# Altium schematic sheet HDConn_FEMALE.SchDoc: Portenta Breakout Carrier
size A3; Author: S. Navaretti; DocumentNumber: ASX00031; Revision: V1.3; SheetNumber: 2; SheetTotal: 6; RevAuthor: Silvio Navaretti
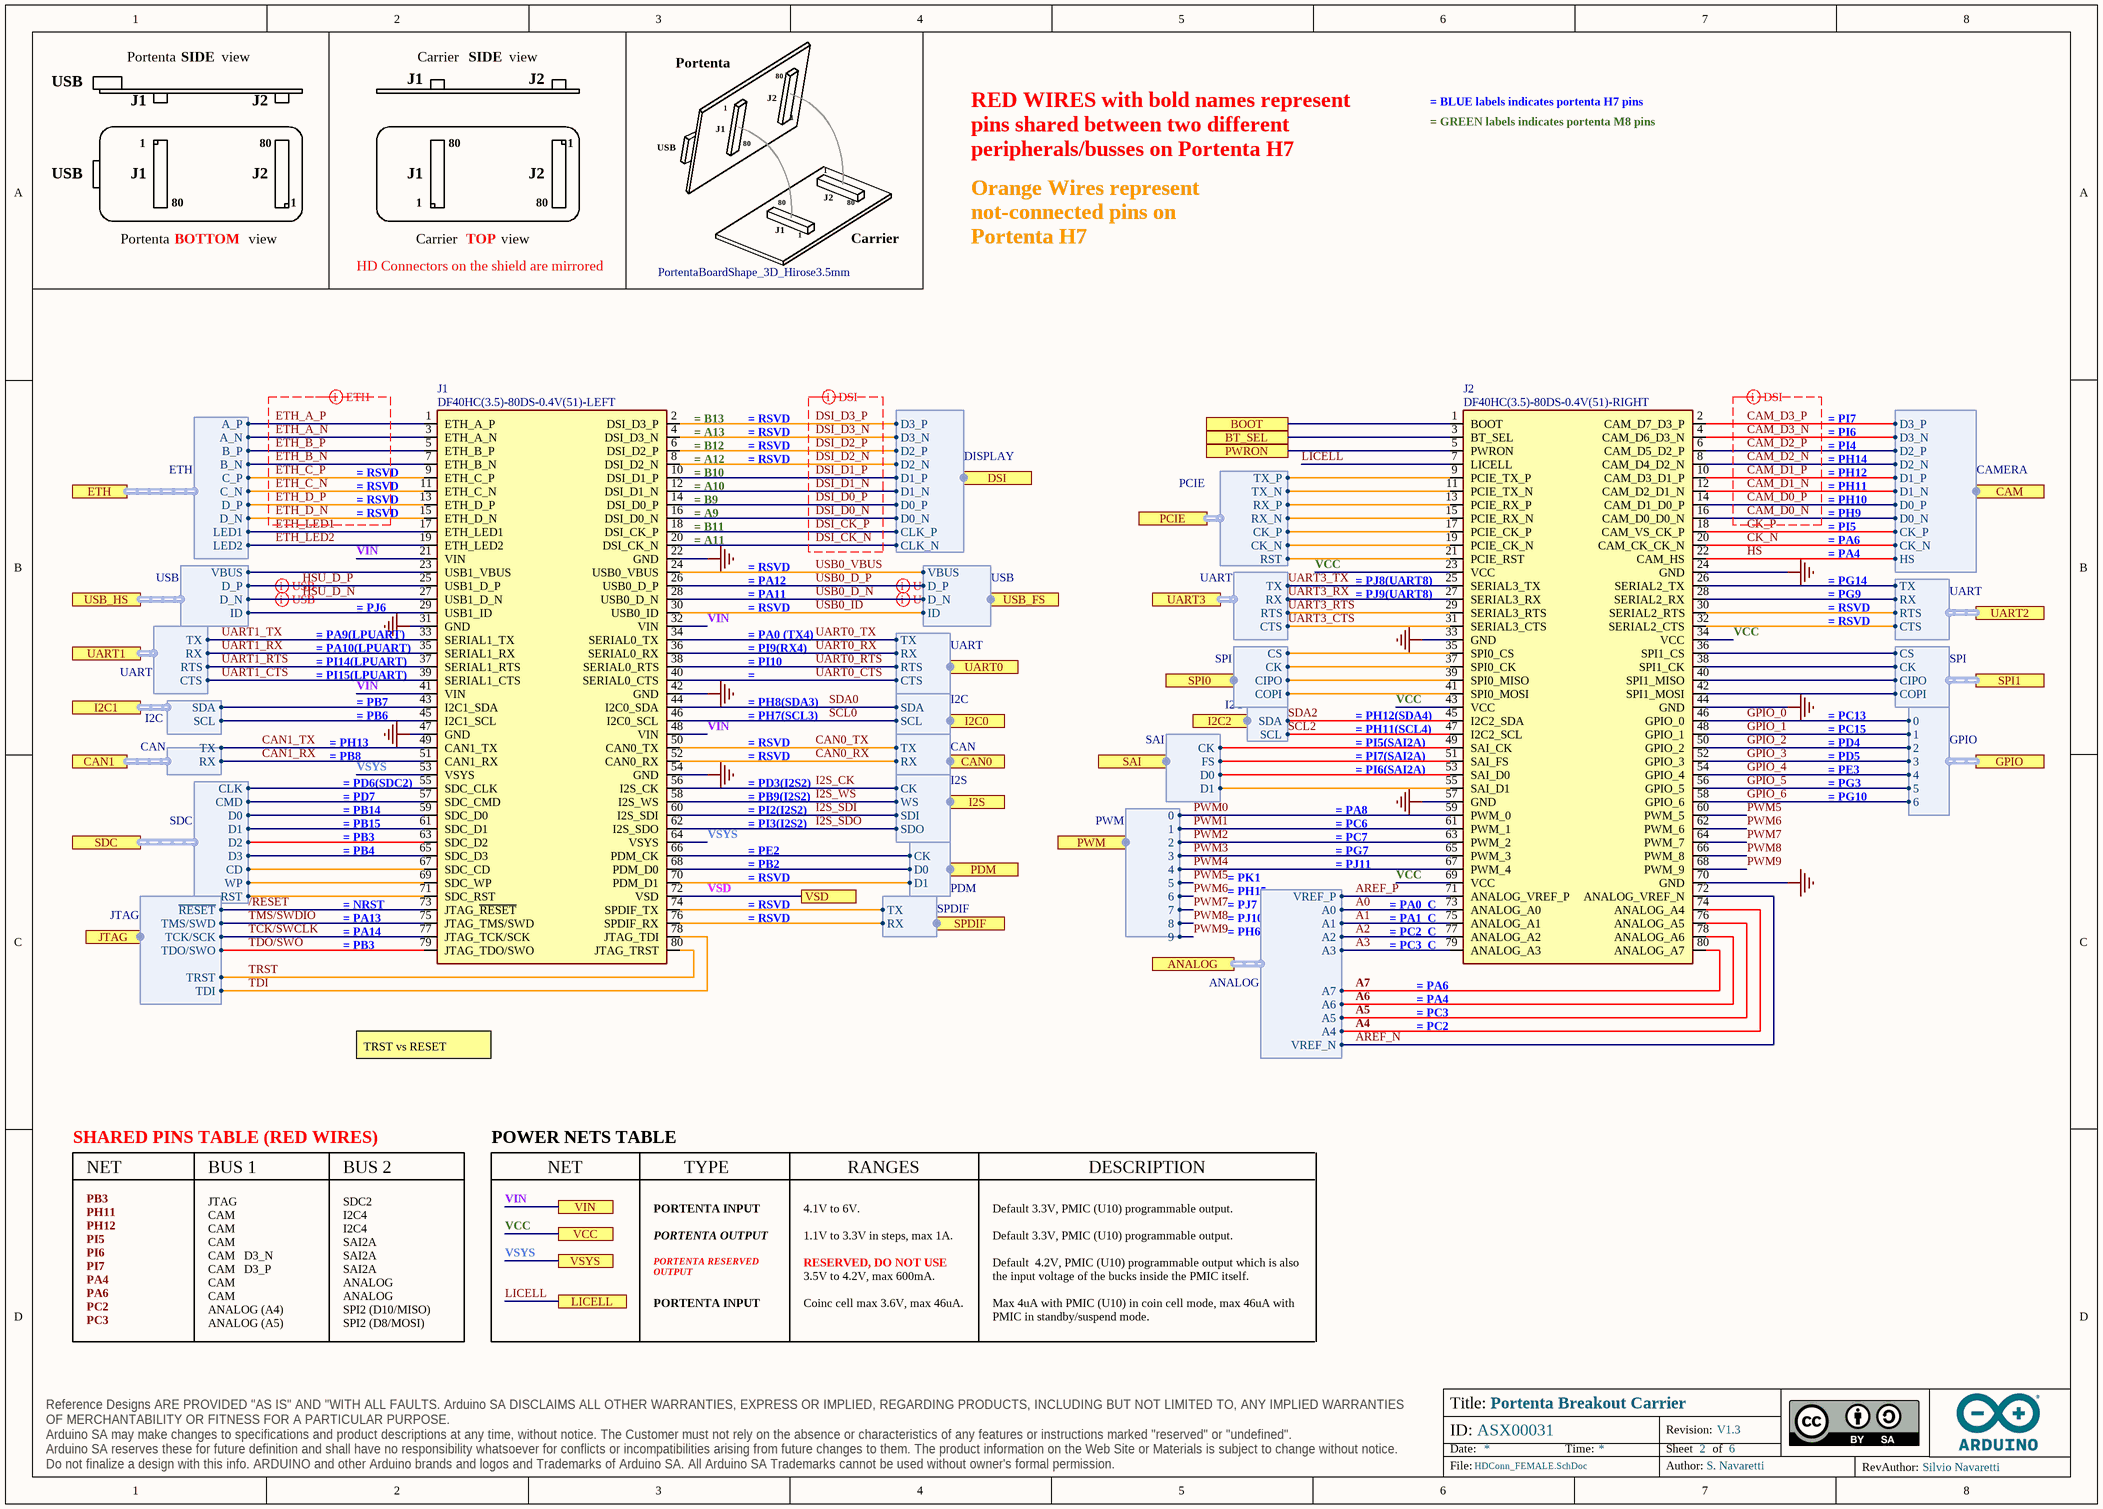
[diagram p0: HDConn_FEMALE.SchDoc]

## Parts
J1  DF40HC(3.5)-80DS-0.4V(51)-LEFT  [DF40HC(3.5)-80DS-0.4V(51)-Footprint-1]
J2  DF40HC(3.5)-80DS-0.4V(51)-RIGHT  [DF40HC(3.5)-80DS-0.4V(51)-Footprint-1]
PortentaBoardShape_3D_Hirose3.5mm  PortentaBoardShape_3D_Hirose3.5mm  [PortentaBoardShape3D-Footprint-1]  (no BOM)

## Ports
ANALOG (harness ANALOG), BOOT, BT_SEL, CAM (harness CAMERA), CAN0 (harness CAN), CAN1 (harness CAN), DSI (harness DISPLAY), ETH (harness ETH), GPIO (harness GPIO), I2C0 (harness I2C), I2C1 (harness I2C), I2C2 (harness I2C), I2S (harness I2S), JTAG (harness JTAG), LICELL, PCIE (harness PCIE), PDM (harness PDM), PWM (harness PWM), PWRON, SAI (harness SAI), SDC (harness SDC), SPDIF (harness SPDIF), SPI0 (harness SPI), SPI1 (harness SPI), UART0 (harness UART), UART1 (harness UART), UART2 (harness UART), UART3 (harness UART), USB_FS (harness USB), USB_HS (harness USB), VCC, VIN, VSD, VSYS

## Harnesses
ANALOG: VREF_P, A0, A1, A2, A3, A7, A6, A5, A4, VREF_N
PWM: 0, 1, 2, 3, 4, 5, 6, 7, 8, 9
GPIO: 0, 1, 2, 3, 4, 5, 6
ETH: A_P, A_N, B_P, B_N, C_P, C_N, D_P, D_N, LED1, LED2
USB: VBUS, D_P, D_N, ID
UART: RX, TX, RTS, CTS
I2C: SCL, SDA
CAN: RX, TX
SDC: CLK, CMD, D0, D1, D2, D3, CD, WP, RST
JTAG: ~{RESET}, TCK/SCK, TDI, TDO/SWO, TMS/SWD, TRST
DISPLAY: CLK_N, CLK_P, D0_N, D0_P, D1_N, D1_P, D2_N, D2_P, D3_N, D3_P
I2C: SDA, SCL
I2S: CK, SDI, SDO, WS
PDM: CK, D0, D1
SAI: CK, FS, D0, D1
CAMERA: D3_P, D3_N, D2_P, D2_N, D1_P, D1_N, D0_P, D0_N, CK_P, CK_N, HS
SPI: CS, CK, CIPO, COPI
PCIE: TX_P, TX_N, RX_P, RX_N, CK_P, CK_N, RST
SPDIF: RX, TX

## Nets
GND: J1.22(GND) J1.31(GND) J1.42(GND) J1.47(GND) J1.54(GND) J2.24(GND) J2.33(GND) J2.44(GND) J2.57(GND) J2.70(GND)
/RESET: J1.73(JTAG_~{RESET}) ; port JTAG.~{RESET}
A0: J2.73(ANALOG_A0) ; port ANALOG.A0
A1: J2.75(ANALOG_A1) ; port ANALOG.A1
A2: J2.77(ANALOG_A2) ; port ANALOG.A2
A3: J2.79(ANALOG_A3) ; port ANALOG.A3
A4: J2.74(ANALOG_A4) ; port ANALOG.A4
A5: J2.76(ANALOG_A5) ; port ANALOG.A5
A6: J2.78(ANALOG_A6) ; port ANALOG.A6
A7: J2.80(ANALOG_A7) ; port ANALOG.A7
AREF_N: J2.72(ANALOG_VREF_N) ; port ANALOG.VREF_N
AREF_P: J2.71(ANALOG_VREF_P) ; port ANALOG.VREF_P
BOOT: J2.1(BOOT) ; port BOOT
BT_SEL: J2.3(BT_SEL) ; port BT_SEL
CAM_D0_N: J2.16(CAM_D0_D0_N) ; port CAM.D0_N
CAM_D0_P: J2.14(CAM_D1_D0_P) ; port CAM.D0_P
CAM_D1_N: J2.12(CAM_D2_D1_N) ; port CAM.D1_N
CAM_D1_P: J2.10(CAM_D3_D1_P) ; port CAM.D1_P
CAM_D2_N: J2.8(CAM_D4_D2_N) ; port CAM.D2_N
CAM_D2_P: J2.6(CAM_D5_D2_P) ; port CAM.D2_P
CAM_D3_N: J2.4(CAM_D6_D3_N) ; port CAM.D3_N
CAM_D3_P: J2.2(CAM_D7_D3_P) ; port CAM.D3_P
CAN0_RX: J1.52(CAN0_RX) ; port CAN0.RX
CAN0_TX: J1.50(CAN0_TX) ; port CAN0.TX
CAN1_RX: J1.51(CAN1_RX) ; port CAN1.RX
CAN1_TX: J1.49(CAN1_TX) ; port CAN1.TX
CK_N: J2.20(CAM_CK_CK_N) ; port CAM.CK_N
CK_P: J2.18(CAM_VS_CK_P) ; port CAM.CK_P
DSI_CK_N: J1.20(DSI_CK_N) ; port DSI.CLK_N
DSI_CK_P: J1.18(DSI_CK_P) ; port DSI.CLK_P
DSI_D0_N: J1.16(DSI_D0_N) ; port DSI.D0_N
DSI_D0_P: J1.14(DSI_D0_P) ; port DSI.D0_P
DSI_D1_N: J1.12(DSI_D1_N) ; port DSI.D1_N
DSI_D1_P: J1.10(DSI_D1_P) ; port DSI.D1_P
DSI_D2_N: J1.8(DSI_D2_N) ; port DSI.D2_N
DSI_D2_P: J1.6(DSI_D2_P) ; port DSI.D2_P
DSI_D3_N: J1.4(DSI_D3_N) ; port DSI.D3_N
DSI_D3_P: J1.2(DSI_D3_P) ; port DSI.D3_P
ETH_A_N: J1.3(ETH_A_N) ; port ETH.A_N
ETH_A_P: J1.1(ETH_A_P) ; port ETH.A_P
ETH_B_N: J1.7(ETH_B_N) ; port ETH.B_N
ETH_B_P: J1.5(ETH_B_P) ; port ETH.B_P
ETH_C_N: J1.11(ETH_C_N) ; port ETH.C_N
ETH_C_P: J1.9(ETH_C_P) ; port ETH.C_P
ETH_D_N: J1.15(ETH_D_N) ; port ETH.D_N
ETH_D_P: J1.13(ETH_D_P) ; port ETH.D_P
ETH_LED1: J1.17(ETH_LED1) ; port ETH.LED1
ETH_LED2: J1.19(ETH_LED2) ; port ETH.LED2
GPIO_0: J2.46(GPIO_0) ; port GPIO.0
GPIO_1: J2.48(GPIO_1) ; port GPIO.1
GPIO_2: J2.50(GPIO_2) ; port GPIO.2
GPIO_3: J2.52(GPIO_3) ; port GPIO.3
GPIO_4: J2.54(GPIO_4) ; port GPIO.4
GPIO_5: J2.56(GPIO_5) ; port GPIO.5
GPIO_6: J2.58(GPIO_6) ; port GPIO.6
HS: J2.22(CAM_HS) ; port CAM.HS
HSU_D_N: J1.27(USB1_D_N) ; port USB_HS.D_N
HSU_D_P: J1.25(USB1_D_P) ; port USB_HS.D_P
I2S_CK: J1.56(I2S_CK) ; port I2S.CK
I2S_SDI: J1.60(I2S_SDI) ; port I2S.SDI
I2S_SDO: J1.62(I2S_SDO) ; port I2S.SDO
I2S_WS: J1.58(I2S_WS) ; port I2S.WS
LICELL: J2.7(LICELL) ; port LICELL
PWM0: J2.59(PWM_0) ; port PWM.0
PWM1: J2.61(PWM_1) ; port PWM.1
PWM2: J2.63(PWM_2) ; port PWM.2
PWM3: J2.65(PWM_3) ; port PWM.3
PWM4: J2.67(PWM_4) ; port PWM.4
PWM5: J2.60(PWM_5) ; port PWM.5
PWM6: J2.62(PWM_6) ; port PWM.6
PWM7: J2.64(PWM_7) ; port PWM.7
PWM8: J2.66(PWM_8) ; port PWM.8
PWM9: J2.68(PWM_9) ; port PWM.9
PWRON: J2.5(PWRON) ; port PWRON
SCL0: J1.46(I2C0_SCL) ; port I2C0.SCL
SCL2: J2.47(I2C2_SCL) ; port I2C2.SCL
SDA0: J1.44(I2C0_SDA) ; port I2C0.SDA
SDA2: J2.45(I2C2_SDA) ; port I2C2.SDA
TCK/SWCLK: J1.77(JTAG_TCK/SCK) ; port JTAG.TCK/SCK
TDI: J1.78(JTAG_TDI) ; port JTAG.TDI
TDO/SWO: J1.79(JTAG_TDO/SWO) ; port JTAG.TDO/SWO
TMS/SWDIO: J1.75(JTAG_TMS/SWD) ; port JTAG.TMS/SWD
TRST: J1.80(JTAG_TRST) ; port JTAG.TRST
UART0_CTS: J1.40(SERIAL0_CTS) ; port UART0.CTS
UART0_RTS: J1.38(SERIAL0_RTS) ; port UART0.RTS
UART0_RX: J1.36(SERIAL0_RX) ; port UART0.RX
UART0_TX: J1.34(SERIAL0_TX) ; port UART0.TX
UART1_CTS: J1.39(SERIAL1_CTS) ; port UART1.CTS
UART1_RTS: J1.37(SERIAL1_RTS) ; port UART1.RTS
UART1_RX: J1.35(SERIAL1_RX) ; port UART1.RX
UART1_TX: J1.33(SERIAL1_TX) ; port UART1.TX
UART3_CTS: J2.31(SERIAL3_CTS) ; port UART3.CTS
UART3_RTS: J2.29(SERIAL3_RTS) ; port UART3.RTS
UART3_RX: J2.27(SERIAL3_RX) ; port UART3.RX
UART3_TX: J2.25(SERIAL3_TX) ; port UART3.TX
USB0_D_N: J1.28(USB0_D_N) ; port USB_FS.D_N
USB0_D_P: J1.26(USB0_D_P) ; port USB_FS.D_P
USB0_ID: J1.30(USB0_ID) ; port USB_FS.ID
USB0_VBUS: J1.24(USB0_VBUS) ; port USB_FS.VBUS
VCC: J2.23(VCC) J2.34(VCC) J2.43(VCC) J2.69(VCC) ; port VCC
VIN: J1.21(VIN) J1.32(VIN) J1.41(VIN) J1.48(VIN) ; port VIN
VSD: J1.72(VSD) ; port VSD
VSYS: J1.53(VSYS) J1.64(VSYS) ; port VSYS
NetJ1_23: J1.23(USB1_VBUS) ; port USB_HS.VBUS
NetJ1_29: J1.29(USB1_ID) ; port USB_HS.ID
NetJ1_43: J1.43(I2C1_SDA) ; port I2C1.SDA
NetJ1_45: J1.45(I2C1_SCL) ; port I2C1.SCL
NetJ1_55: J1.55(SDC_CLK) ; port SDC.CLK
NetJ1_57: J1.57(SDC_CMD) ; port SDC.CMD
NetJ1_59: J1.59(SDC_D0) ; port SDC.D0
NetJ1_61: J1.61(SDC_D1) ; port SDC.D1
NetJ1_63: J1.63(SDC_D2) ; port SDC.D2
NetJ1_65: J1.65(SDC_D3) ; port SDC.D3
NetJ1_66: J1.66(PDM_CK) ; port PDM.CK
NetJ1_67: J1.67(SDC_CD) ; port SDC.CD
NetJ1_68: J1.68(PDM_D0) ; port PDM.D0
NetJ1_69: J1.69(SDC_WP) ; port SDC.WP
NetJ1_70: J1.70(PDM_D1) ; port PDM.D1
NetJ1_71: J1.71(SDC_RST) ; port SDC.RST
NetJ1_74: J1.74(SPDIF_TX) ; port SPDIF.TX
NetJ1_76: J1.76(SPDIF_RX) ; port SPDIF.RX
NetJ2_9: J2.9(PCIE_TX_P) ; port PCIE.TX_P
NetJ2_11: J2.11(PCIE_TX_N) ; port PCIE.TX_N
NetJ2_13: J2.13(PCIE_RX_P) ; port PCIE.RX_P
NetJ2_15: J2.15(PCIE_RX_N) ; port PCIE.RX_N
NetJ2_17: J2.17(PCIE_CK_P) ; port PCIE.CK_P
NetJ2_19: J2.19(PCIE_CK_N) ; port PCIE.CK_N
NetJ2_21: J2.21(PCIE_RST) ; port PCIE.RST
NetJ2_26: J2.26(SERIAL2_TX) ; port UART2.TX
NetJ2_28: J2.28(SERIAL2_RX) ; port UART2.RX
NetJ2_30: J2.30(SERIAL2_RTS) ; port UART2.RTS
NetJ2_32: J2.32(SERIAL2_CTS) ; port UART2.CTS
NetJ2_35: J2.35(SPI0_CS) ; port SPI0.CS
NetJ2_36: J2.36(SPI1_CS) ; port SPI1.CS
NetJ2_37: J2.37(SPI0_CK) ; port SPI0.CK
NetJ2_38: J2.38(SPI1_CK) ; port SPI1.CK
NetJ2_39: J2.39(SPI0_MISO) ; port SPI0.CIPO
NetJ2_40: J2.40(SPI1_MISO) ; port SPI1.CIPO
NetJ2_41: J2.41(SPI0_MOSI) ; port SPI0.COPI
NetJ2_42: J2.42(SPI1_MOSI) ; port SPI1.COPI
NetJ2_49: J2.49(SAI_CK) ; port SAI.CK
NetJ2_51: J2.51(SAI_FS) ; port SAI.FS
NetJ2_53: J2.53(SAI_D0) ; port SAI.D0
NetJ2_55: J2.55(SAI_D1) ; port SAI.D1

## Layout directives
differential pair; differential pair class ETH: ETH_A_N, ETH_A_P, ETH_B_N, ETH_B_P, ETH_C_N, ETH_C_P, ETH_D_N, ETH_D_P
differential pair; differential pair class USB: HSU_D_N, HSU_D_P, USB0_D_N, USB0_D_P
differential pair; differential pair class DSI: DSI_CK_N, DSI_CK_P, DSI_D0_N, DSI_D0_P, DSI_D1_N, DSI_D1_P, DSI_D2_N, DSI_D2_P, DSI_D3_N, DSI_D3_P
differential pair; differential pair class CAM: CAM_D0_N, CAM_D0_P, CAM_D1_N, CAM_D1_P, CAM_D2_N, CAM_D2_P, CAM_D3_N, CAM_D3_P

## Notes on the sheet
- USB
- Portenta
- J1
- SIDE
- view
- J2
- Carrier
- COLOR LEGEND:
- 1
- 80
- RED WIRES with bold names represent pins shared between two different peripherals/busses on Portenta H7
- BOTTOM
- TOP
- (near PortentaBoardShape_3D_Hirose3.5mm) HD Connectors on the shield are mirrored
- Orange Wires represent not-connected pins on Portenta H7
- TRST vs RESET
- SHARED PINS TABLE (RED WIRES)
- NET
- BUS 1
- BUS 2
- POWER NETS TABLE
- TYPE
- RANGES
- DESCRIPTION
- JTAG
- CAM
- CAM   D3_N
- SDC2
- I2C4
- SAI2A
- PORTENTA INPUT
- PORTENTA OUTPUT
- 4.1V to 6V.
- 1.1V to 3.3V in steps, max 1A.
- RESERVED, DO NOT USE
- Default 3.3V, PMIC (U10) programmable output.
- ANALOG (A4)
- ANALOG (A5)
- CAM   D3_P
- ANALOG
- SPI2 (D10/MISO)
- SPI2 (D8/MOSI)
- PORTENTA RESERVED OUTPUT
- Coinc cell max 3.6V, max 46uA.
- 3.5V to 4.2V, max 600mA.
- Default  4.2V, PMIC (U10) programmable output which is also the input voltage of the bucks inside the PMIC itself.
- Max 4uA with PMIC (U10) in coin cell mode, max 46uA with PMIC in standby/suspend mode.
- Labels drawn without touching a wire or pin: PA4, PA6, PB3, PC2, PC3, PH11, PH12, PI5, PI6, PI7

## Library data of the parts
J1 = J0016-A.10: CONN RCPT FEMALE D80POS 0.4MM SMD GOLD; Manufacturer: Hirose; Number of Contacts: 80; Current Rating: 300mA; Voltage Rating: 30V; Stack Height: 3.5mm; Code Arduino: J0016; Gender: Receptacle; Pitch: 0.016inch
J2 = J0153-A.2: CONN RCPT FEMALE D80POS 0.4MM SMD GOLD; Manufacturer: Hirose; Number of Contacts: 80; Current Rating: 300mA; Voltage Rating: 30V; Stack Height: 3.5mm; Code Arduino: J0016; Gender: Receptacle; Pitch: 0.016inch
PortentaBoardShape_3D_Hirose3.5mm = UT0026-A.2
